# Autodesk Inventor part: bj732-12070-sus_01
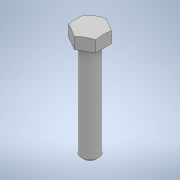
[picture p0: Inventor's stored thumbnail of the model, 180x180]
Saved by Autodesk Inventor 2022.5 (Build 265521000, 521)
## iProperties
Part Number: bj732-12070-sus_01
Material: 一般
Document SubType Name: Modeling
Designer: ImaoCorp
Density: 1 g/cm^3
Appearance: 既定
Author: ImaoCorp
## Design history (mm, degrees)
feature "bj732-12070-sus_01"
node "ソリッド1"
